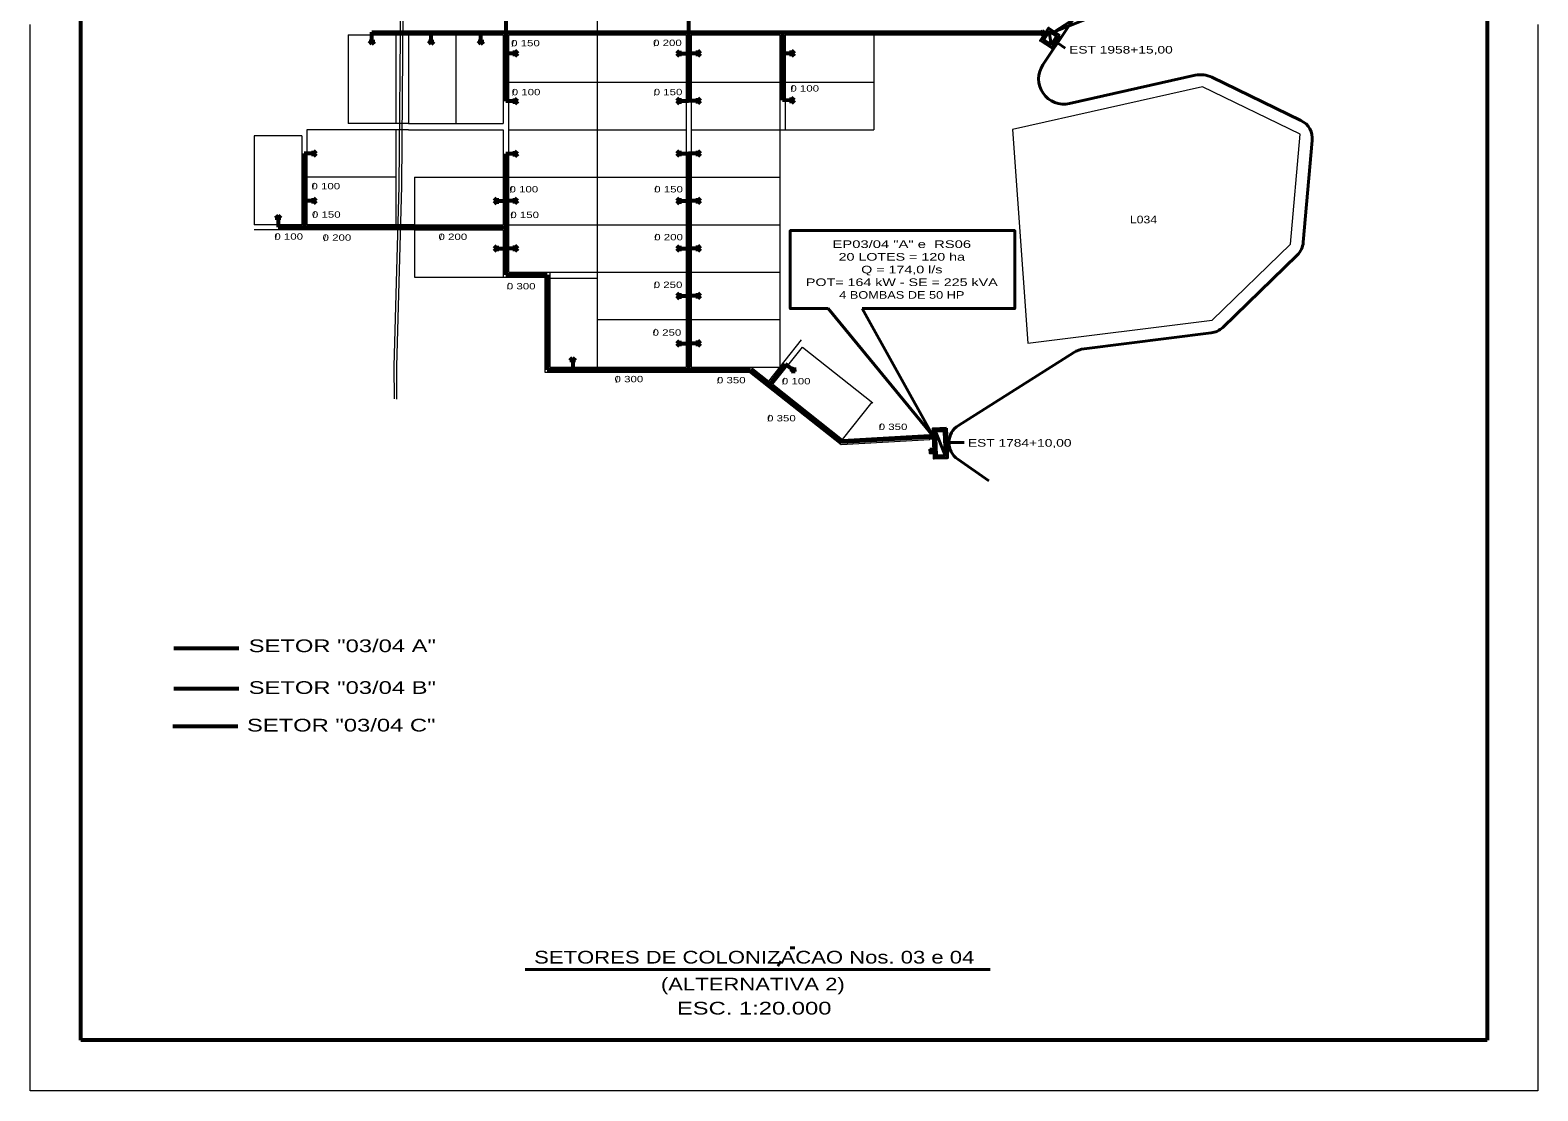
# Model space of a CAD drawing. Extents: x 312964 to 351929, y 9004151 to 9034973.
# Drawn here: x 326200 to 332140, y 9013358 to 9017535 of the extents above; entities that cross this region are included whole.
import ezdxf
from ezdxf.enums import TextEntityAlignment as Align

# ---------------------------------------------------------------- set-up
doc = ezdxf.new("R2010")
doc.units = 0
doc.header["$LTSCALE"] = 10
for name, color, linetype, lineweight in [('1', 7, 'Continuous', 13), ('2', 7, 'Continuous', 53), ('3', 7, 'Continuous', 13), ('6', 7, 'Continuous', 13)]:
    doc.layers.add(name, color=color, linetype=linetype, lineweight=lineweight)

msp = doc.modelspace()

# ---------------------------------------------------------------- linework, layer by layer
at = {"layer": '1', "lineweight": 53}
for p, q in [((326400.21, 9013557.86), (326400.21, 9021257.86)), ((331940.21, 9021257.86), (331940.21, 9013557.86)), ((326766.28, 9015101.17), (327022.23, 9015101.17)), ((326766.28, 9014942.16), (327022.23, 9014942.16)), ((331940.21, 9013557.86), (326400.21, 9013557.86))]:
    msp.add_line(p, q, dxfattribs=at)
at = {"layer": '1'}
for p, q in [((328434.4, 9018098.18), (328434.4, 9016208.18)), ((327453.4, 9017517.18), (328064.4, 9017517.18)), ((327453.4, 9017517.18), (327453.4, 9017167.18)), ((327640.4, 9017517.18), (327640.4, 9017167.18)), ((327690.4, 9017517.18), (327690.4, 9017167.18)), ((327877.4, 9017517.18), (327877.4, 9017167.18)), ((328064.4, 9017517.18), (328064.4, 9017167.18)), ((328084.4, 9017517.18), (328784.4, 9017517.18)), ((328084.4, 9017517.18), (328084.4, 9017143.18)), ((328784.4, 9017517.18), (328784.4, 9017143.18)), ((328804.4, 9017517.18), (329154.4, 9017517.18)), ((328804.4, 9017517.18), (328804.4, 9017143.18)), ((329154.4, 9017517.18), (329154.4, 9017143.18)), ((329174.4, 9017517.18), (330185.67, 9017517.18)), ((329174.4, 9017517.18), (329174.4, 9017143.18)), ((329524.4, 9017517.18), (329524.4, 9017143.18)), ((328084.4, 9017330.18), (328784.4, 9017330.18)), ((328804.4, 9017330.18), (329154.4, 9017330.18)), ((329174.4, 9017330.18), (329524.4, 9017330.18)), ((327690.4, 9017167.18), (327453.4, 9017167.18)), ((327690.4, 9017167.18), (328064.4, 9017167.18)), ((327083.4, 9017119.18), (327083.4, 9016769.18)), ((327270.4, 9017119.18), (327083.4, 9017119.18)), ((327270.4, 9017119.18), (327270.4, 9016769.18)), ((327690.4, 9017143.18), (327290.4, 9017143.18)), ((327290.4, 9017143.18), (327290.4, 9016769.18)), ((327640.4, 9017143.18), (327640.4, 9016769.18)), ((327690.4, 9017143.18), (328064.4, 9017143.18)), ((328064.4, 9017143.18), (328064.4, 9016769.18)), ((328084.4, 9017143.18), (328784.4, 9017143.18)), ((328084.4, 9017143.18), (328784.4, 9017143.18)), ((328084.4, 9017143.18), (328084.4, 9016582.18)), ((328784.4, 9017143.18), (328784.4, 9016208.18)), ((328804.4, 9017143.18), (329524.4, 9017143.18)), ((328804.4, 9017143.18), (328804.4, 9016208.18)), ((328804.4, 9017143.18), (329154.4, 9017143.18)), ((329154.4, 9017143.18), (329154.4, 9016208.18)), ((329174.4, 9017143.18), (329524.4, 9017143.18)), ((327640.4, 9016956.18), (327290.4, 9016956.18)), ((327714.4, 9016956.18), (328064.4, 9016956.18)), ((327714.4, 9016956.18), (327714.4, 9016769.18)), ((328084.4, 9016956.18), (328784.4, 9016956.18)), ((328804.4, 9016956.18), (329154.4, 9016956.18)), ((327270.4, 9016769.18), (327083.4, 9016769.18)), ((327236.67, 9016769.18), (327083.4, 9016769.18)), ((327714.4, 9016769.18), (327290.4, 9016769.18)), ((327714.4, 9016769.18), (328064.4, 9016769.18)), ((327714.4, 9016749.18), (328064.4, 9016749.18)), ((327714.4, 9016749.18), (327714.4, 9016562.18)), ((328064.4, 9016749.18), (328064.4, 9016562.18)), ((328084.4, 9016769.18), (328784.4, 9016769.18)), ((328804.4, 9016769.18), (329154.4, 9016769.18)), ((328084.4, 9016582.18), (328784.4, 9016582.18)), ((328247.4, 9016582.18), (328247.4, 9016208.18)), ((328804.4, 9016582.18), (329154.4, 9016582.18)), ((327714.4, 9016562.18), (328064.4, 9016562.18)), ((328064.4, 9016562.18), (328227.4, 9016562.18)), ((328227.4, 9016562.18), (328227.4, 9016188.18)), ((328247.4, 9016558.18), (328434.4, 9016558.18)), ((328434.4, 9016395.18), (328784.4, 9016395.18)), ((328804.4, 9016395.18), (329154.4, 9016395.18)), ((329110.89, 9016153.06), (329239.15, 9016315.53)), ((329126.58, 9016140.67), (329242.46, 9016287.44)), ((329242.46, 9016287.44), (329520.73, 9016067.75)), ((328247.4, 9016208.18), (328784.4, 9016208.18)), ((328804.4, 9016208.18), (329154.4, 9016208.18)), ((329041.07, 9016208.18), (329110.89, 9016153.06)), ((328227.4, 9016188.18), (329034.12, 9016188.18)), ((329034.12, 9016188.18), (329394.86, 9015903.39)), ((329126.58, 9016140.67), (329401.29, 9015923.79)), ((329401.29, 9015923.79), (329517.17, 9016070.57)), ((329394.86, 9015903.39), (329744.27, 9015923.47)), ((329401.29, 9015923.79), (329743.12, 9015943.43))]:
    msp.add_line(p, q, dxfattribs=at)
at = {"layer": '1', "lineweight": 40}
for p, q in [((330190.37, 9017399.2), (330425.64, 9017751.37)), ((330200.76, 9017525.23), (330179.99, 9017520.91)), ((330192.53, 9017512.68), (330188.21, 9017533.45)), ((330215.51, 9017529.5), (330222.42, 9017479.14)), ((330790.76, 9017357.5), (330295.47, 9017246.08)), ((331206.79, 9017179.77), (330856.38, 9017349.9)), ((331216.03, 9016699.82), (331251.54, 9017100.74)), ((330898.62, 9016364.83), (331192.04, 9016649.46)), ((330352.57, 9016280.45), (330852.83, 9016342.87)), ((329857.41, 9015978.67), (330311.52, 9016265.74)), ((329758.69, 9015929.02), (329743.12, 9015943.43)), ((329758.11, 9015944.01), (329743.7, 9015928.45)), ((329801.02, 9015957.32), (329802.49, 9015919.03)), ((329810.63, 9015967.7), (329812.87, 9015909.42)), ((329760.85, 9015870.74), (329745.31, 9015885.18)), ((329760.3, 9015885.73), (329745.85, 9015870.19)), ((329803.24, 9015898.95), (329804.63, 9015860.66)), ((329977.3, 9015760.07), (329854.53, 9015845.34)), ((329195.04, 9013921.59), (329213.33, 9013921.59)), ((328150.5, 9013836.35), (329981.83, 9013836.35)), ((329158.39, 9013869.07), (329145.73, 9013849.36))]:
    msp.add_line(p, q, dxfattribs=at)
at = {"layer": '1'}
for points in [[(332140.21, 9017557.86), (332140.21, 9013357.86), (326200.21, 9013357.86), (326200.21, 9017557.86)], [(330131.21, 9016303.21), (330856.6, 9016393.72), (331165.24, 9016693.12), (331203.56, 9017125.76), (330818.8, 9017312.56), (330070.41, 9017144.21)], [(327714.4, 9016749.18), (327290.4, 9016749.18), (327083.4, 9016749.18)]]:
    msp.add_lwpolyline(points, dxfattribs=at)
at = {"layer": '1', "lineweight": 40}
for points in [[(330188.21, 9017533.45), (330179.99, 9017520.91), (330192.53, 9017512.68), (330200.76, 9017525.23)], [(330257.28, 9017514.07), (330225.3, 9017465.29), (330180.65, 9017494.57), (330212.63, 9017543.34)], [(330243.44, 9017511.19), (330222.42, 9017479.14), (330194.5, 9017497.45), (330215.51, 9017529.5)], [(330215.51, 9017529.5), (330243.44, 9017511.19), (330222.42, 9017479.14)], [(329743.12, 9015943.43), (329743.7, 9015928.45), (329758.69, 9015929.02), (329758.11, 9015944.01)], [(329767.66, 9015956.05), (329801.02, 9015957.32), (329804.63, 9015860.66)], [(329745.31, 9015885.18), (329745.85, 9015870.19), (329760.85, 9015870.74), (329760.3, 9015885.73)]]:
    msp.add_lwpolyline(points, close=True, dxfattribs=at)
for points in [[(329759.52, 9015907.37), (329757.28, 9015965.65), (329810.63, 9015967.7)], [(329769.87, 9015897.74), (329767.66, 9015956.05), (329801.02, 9015957.32)], [(329812.87, 9015909.31), (329814.98, 9015851.02), (329761.63, 9015849.09), (329759.52, 9015907.37)], [(329803.24, 9015898.95), (329804.63, 9015860.66), (329771.26, 9015859.45), (329769.87, 9015897.74)]]:
    msp.add_lwpolyline(points, dxfattribs=at)
for centre, radius, start, end in [((330273.52, 9017343.65), 100, 146.25469, 282.67773), ((330812.71, 9017259.94), 100, 64.10269, 102.67774), ((331171.85, 9017107.8), 80, 354.93858, 64.10274), ((331136.34, 9016706.88), 80, 314.12934, 354.9386), ((330842.92, 9016422.25), 80, 277.11219, 314.12931), ((330364.95, 9016181.22), 100, 97.11218, 122.3), ((329900.16, 9015911.05), 80, 122.29999, 235.22056)]:
    msp.add_arc(centre, radius, start, end, dxfattribs=at)
at = {"layer": '2', "lineweight": 40}
for p, q in [((330545.86, 9017730.28), (330234.96, 9017528.71)), ((330550.35, 9017653.91), (330234.96, 9017528.71)), ((330247.91, 9017485.33), (330278.33, 9017465.01)), ((329820.17, 9015911.97), (329879.5, 9015911.29))]:
    msp.add_line(p, q, dxfattribs=at)
at = {"layer": '2'}
for p, q in [((327546.78, 9017491.33), (327546.9, 9017527.18)), ((327779.73, 9017491.33), (327779.85, 9017527.18)), ((327976.1, 9017491.33), (327976.22, 9017527.18)), ((329164.4, 9017527.18), (329164.4, 9017259.07)), ((327536.26, 9017491.37), (327557.82, 9017491.3)), ((327547, 9017480.55), (327536.26, 9017491.37)), ((327547, 9017480.55), (327557.82, 9017491.3)), ((327769.21, 9017491.37), (327790.76, 9017491.3)), ((327779.95, 9017480.55), (327769.21, 9017491.37)), ((327779.95, 9017480.55), (327790.76, 9017491.3)), ((327965.58, 9017491.37), (327987.14, 9017491.3)), ((327976.32, 9017480.55), (327965.58, 9017491.37)), ((327976.32, 9017480.55), (327987.14, 9017491.3)), ((328110.21, 9017433.04), (328110.29, 9017454.6)), ((328121.03, 9017443.78), (328110.29, 9017454.6)), ((328830.21, 9017433.04), (328830.29, 9017454.6)), ((328841.03, 9017443.78), (328830.29, 9017454.6)), ((329200.21, 9017433.04), (329200.29, 9017454.6)), ((329211.03, 9017443.78), (329200.29, 9017454.6)), ((330241.29, 9017489.68), (330247.88, 9017485.28)), ((328110.25, 9017443.56), (328074.4, 9017443.68)), ((328121.03, 9017443.78), (328110.21, 9017433.04)), ((328747.77, 9017443.58), (328758.59, 9017454.32)), ((328747.77, 9017443.58), (328758.52, 9017432.76)), ((328758.59, 9017454.32), (328758.52, 9017432.76)), ((328758.55, 9017443.8), (328794.4, 9017443.68)), ((328830.25, 9017443.56), (328794.4, 9017443.68)), ((328841.03, 9017443.78), (328830.21, 9017433.04)), ((329200.25, 9017443.56), (329164.4, 9017443.68)), ((329211.03, 9017443.78), (329200.21, 9017433.04)), ((328110.25, 9017255.3), (328074.4, 9017255.42)), ((328110.21, 9017244.78), (328110.29, 9017266.34)), ((328121.03, 9017255.52), (328110.21, 9017244.78)), ((328121.03, 9017255.52), (328110.29, 9017266.34)), ((328747.77, 9017256.58), (328758.59, 9017267.32)), ((328747.77, 9017256.58), (328758.52, 9017245.76)), ((328758.59, 9017267.32), (328758.52, 9017245.76)), ((328758.55, 9017256.8), (328794.4, 9017256.68)), ((328830.25, 9017256.56), (328794.4, 9017256.68)), ((328830.21, 9017246.04), (328830.29, 9017267.6)), ((328841.03, 9017256.78), (328830.21, 9017246.04)), ((328841.03, 9017256.78), (328830.29, 9017267.6)), ((329200.25, 9017258.95), (329164.4, 9017259.07)), ((329200.21, 9017248.43), (329200.29, 9017269.99)), ((329211.03, 9017259.17), (329200.21, 9017248.43)), ((329211.03, 9017259.17), (329200.29, 9017269.99)), ((327280.4, 9017049.62), (327280.4, 9016759.18)), ((327316.25, 9017049.5), (327280.4, 9017049.62)), ((327316.21, 9017038.97), (327316.29, 9017060.53)), ((327327.03, 9017049.72), (327316.21, 9017038.97)), ((327327.03, 9017049.72), (327316.29, 9017060.53)), ((328074.4, 9017048.41), (328074.4, 9016572.18)), ((328110.25, 9017048.29), (328074.4, 9017048.41)), ((328110.21, 9017037.77), (328110.29, 9017059.33)), ((328121.03, 9017048.51), (328110.21, 9017037.77)), ((328121.03, 9017048.51), (328110.29, 9017059.33)), ((328747.77, 9017049.58), (328758.59, 9017060.32)), ((328747.77, 9017049.58), (328758.52, 9017038.76)), ((328758.59, 9017060.32), (328758.52, 9017038.76)), ((328758.55, 9017049.8), (328794.4, 9017049.68)), ((328794.4, 9017049.68), (328794.4, 9016198.18)), ((328830.25, 9017049.56), (328794.4, 9017049.68)), ((328830.21, 9017039.04), (328830.29, 9017060.6)), ((328841.03, 9017049.78), (328830.21, 9017039.04)), ((328841.03, 9017049.78), (328830.29, 9017060.6)), ((327316.25, 9016862.56), (327280.4, 9016862.68)), ((327316.21, 9016852.04), (327316.29, 9016873.6)), ((327327.03, 9016862.78), (327316.21, 9016852.04)), ((327327.03, 9016862.78), (327316.29, 9016873.6)), ((328027.77, 9016862.58), (328038.59, 9016873.32)), ((328027.77, 9016862.58), (328038.52, 9016851.76)), ((328038.59, 9016873.32), (328038.52, 9016851.76)), ((328038.55, 9016862.8), (328074.4, 9016862.68)), ((328110.25, 9016862.56), (328074.4, 9016862.68)), ((328110.21, 9016852.04), (328110.29, 9016873.6)), ((328121.03, 9016862.78), (328110.21, 9016852.04)), ((328121.03, 9016862.78), (328110.29, 9016873.6)), ((328747.77, 9016862.58), (328758.59, 9016873.32)), ((328747.77, 9016862.58), (328758.52, 9016851.76)), ((328758.59, 9016873.32), (328758.52, 9016851.76)), ((328758.55, 9016862.8), (328794.4, 9016862.68)), ((328830.25, 9016862.56), (328794.4, 9016862.68)), ((328830.21, 9016852.04), (328830.29, 9016873.6)), ((328841.03, 9016862.78), (328830.21, 9016852.04)), ((328841.03, 9016862.78), (328830.29, 9016873.6)), ((327176.8, 9016805.81), (327165.98, 9016795.07)), ((327176.8, 9016805.81), (327187.54, 9016794.99)), ((327187.54, 9016794.99), (327165.98, 9016795.07)), ((327177.02, 9016795.03), (327176.9, 9016759.18)), ((327176.9, 9016759.18), (328074.4, 9016759.18)), ((328027.77, 9016675.58), (328038.59, 9016686.32)), ((328038.59, 9016686.32), (328038.52, 9016664.76)), ((328110.21, 9016665.04), (328110.29, 9016686.6)), ((328121.03, 9016675.78), (328110.29, 9016686.6)), ((328747.77, 9016675.58), (328758.59, 9016686.32)), ((328758.59, 9016686.32), (328758.52, 9016664.76)), ((328830.21, 9016665.04), (328830.29, 9016686.6)), ((328841.03, 9016675.78), (328830.29, 9016686.6)), ((328027.77, 9016675.58), (328038.52, 9016664.76)), ((328038.55, 9016675.8), (328074.4, 9016675.68)), ((328110.25, 9016675.56), (328074.4, 9016675.68)), ((328121.03, 9016675.78), (328110.21, 9016665.04)), ((328747.77, 9016675.58), (328758.52, 9016664.76)), ((328758.55, 9016675.8), (328794.4, 9016675.68)), ((328830.25, 9016675.56), (328794.4, 9016675.68)), ((328841.03, 9016675.78), (328830.21, 9016665.04)), ((328074.4, 9016572.18), (328237.4, 9016572.18)), ((328237.4, 9016572.18), (328237.4, 9016198.18)), ((328747.77, 9016488.58), (328758.59, 9016499.32)), ((328747.77, 9016488.58), (328758.52, 9016477.76)), ((328758.59, 9016499.32), (328758.52, 9016477.76)), ((328758.55, 9016488.8), (328794.4, 9016488.68)), ((328830.25, 9016488.56), (328794.4, 9016488.68)), ((328830.21, 9016478.04), (328830.29, 9016499.6)), ((328841.03, 9016488.78), (328830.21, 9016478.04)), ((328841.03, 9016488.78), (328830.29, 9016499.6)), ((328747.77, 9016301.58), (328758.59, 9016312.32)), ((328747.77, 9016301.58), (328758.52, 9016290.76)), ((328758.59, 9016312.32), (328758.52, 9016290.76)), ((328758.55, 9016301.8), (328794.4, 9016301.68)), ((328830.25, 9016301.56), (328794.4, 9016301.68)), ((328830.21, 9016291.04), (328830.29, 9016312.6)), ((328841.03, 9016301.78), (328830.21, 9016291.04)), ((328841.03, 9016301.78), (328830.29, 9016312.6)), ((328337.51, 9016244.81), (328326.69, 9016234.07)), ((328348.25, 9016233.99), (328326.69, 9016234.07)), ((328337.51, 9016244.81), (328348.25, 9016233.99)), ((328337.73, 9016234.03), (328337.61, 9016198.18)), ((329204.73, 9016197.94), (329176.67, 9016220.25)), ((328237.4, 9016198.18), (329037.6, 9016198.18)), ((329198.19, 9016189.71), (329211.6, 9016206.58)), ((329213.33, 9016191.44), (329198.19, 9016189.71)), ((329213.33, 9016191.44), (329211.6, 9016206.58)), ((329112.54, 9016139.02), (329398.08, 9015913.59)), ((329398.08, 9015913.59), (329743.7, 9015933.45)), ((329812.87, 9015909.42), (329820.17, 9015909.56)), ((326762.05, 9014794.08), (327018, 9014794.08))]:
    msp.add_line(p, q, dxfattribs=at)
for points in [[(328074.4, 9018003.02), (328074.4, 9017527.18), (328074.4, 9017255.42)], [(328794.4, 9018002.65), (328794.4, 9017527.18), (328794.4, 9017256.68)], [(327546.9, 9017527.18), (328064.4, 9017527.18), (328784.4, 9017527.18), (329154.4, 9017527.18), (330184.1, 9017527.18)], [(329037.6, 9016198.18), (329112.54, 9016139.02), (329176.67, 9016220.25)]]:
    msp.add_lwpolyline(points, dxfattribs=at)
at = {"layer": '2', "lineweight": 40}
for points in [[(329195.16, 9016655.42), (329195.16, 9016745.85), (329372.65, 9016745.85)], [(329372.65, 9016745.85), (330079.39, 9016745.85), (330079.39, 9016439.03), (329478.8, 9016439.03)], [(329344.14, 9016439.03), (329195.16, 9016439.03), (329195.16, 9016655.42)], [(329344.14, 9016439.03), (329758.4, 9015936.51), (329478.8, 9016439.03)]]:
    msp.add_lwpolyline(points, dxfattribs=at)
at = {"layer": '3'}
msp.add_line((330070.41, 9017144.21), (330131.21, 9016303.21), dxfattribs=at)
at = {"layer": '6'}
for p, q in [((327654.4, 9016921.26), (327664.4, 9018138.26)), ((327634.41, 9016210.46), (327654.41, 9016921.46)), ((327635.24, 9016082.67), (327634.4, 9016210.12))]:
    msp.add_line(p, q, dxfattribs=at)
msp.add_lwpolyline([(327645.24, 9016081.85), (327644.4, 9016210.18), (327664.4, 9016921.18), (327674.4, 9018138.18)], dxfattribs=at)

# ---------------------------------------------------------------- texts
at = {"layer": '1'}
for s, width, p in [('SETOR "03/04 A"', 1.4, (327430.05, 9015085.66)), ('SETOR "03/04 B"', 1.4, (327430.05, 9014921.17)), ('SETOR "03/04 C"', 1.4, (327425.82, 9014773.08)), ('SETORES DE COLONIZACAO Nos. 03 e 04', 1.3, (329052.89, 9013859.22)), ('(ALTERNATIVA 2)', 1.3, (329047.45, 9013753.1)), ('ESC. 1:20.000', 1.4, (329052.71, 9013658.46))]:
    msp.add_text(s, height=50, dxfattribs=dict(at, width=width)).set_placement(p, align=Align.CENTER)
at = {"layer": '2'}
for s, height, width, p in [('0 150', 25, 1.35, (328151.63, 9017471.88)), ('0 200', 25, 1.35, (328710.87, 9017472.94)), ('EST 1958+15,00', 30, 1.35, (330497.73, 9017443.15)), ('0 100', 25, 1.35, (328154.01, 9017278.99)), ('0 150', 25, 1.35, (328713.38, 9017279.19)), ('0 100', 25, 1.35, (329251.83, 9017293.49)), ('0 100', 25, 1.35, (327364.96, 9016908.5)), ('0 100', 25, 1.35, (328145.37, 9016896.19)), ('0 150', 25, 1.35, (328715.49, 9016896.19)), ('0 150', 25, 1.35, (327366.94, 9016796.67)), ('0 150', 25, 1.35, (328148.48, 9016795.19)), ('0 100', 25, 1.35, (327218.85, 9016710.06)), ('0 200', 25, 1.35, (327408.89, 9016705.83)), ('0 200', 25, 1.35, (327865.6, 9016709.2)), ('0 200', 25, 1.35, (328715.55, 9016707.77)), ('EP03/04 "A" e  RS06', 30, 1.45, (329634.34, 9016677.51)), ('20 LOTES = 120 ha', 30, 1.4, (329634.34, 9016627.51)), ('Q = 174,0 l/s', 30, 1.4, (329634.34, 9016577.51)), ('0 300', 25, 1.35, (328134.82, 9016514.3)), ('0 250', 25, 1.35, (328713.38, 9016520.11)), ('POT= 164 kW - SE = 225 kVA', 30, 1.4, (329634.34, 9016527.51)), ('4 BOMBAS DE 50 HP', 30, 1.25, (329634.34, 9016477.51)), ('0 250', 25, 1.35, (328709.16, 9016332.03)), ('0 300', 25, 1.35, (328559.24, 9016148.7)), ('0 350', 25, 1.35, (328962.55, 9016144.47)), ('0 100', 25, 1.35, (329218.34, 9016140.38)), ('0 350', 25, 1.35, (329159.99, 9015994.38)), ('0 350', 25, 1.35, (329599.87, 9015960.69)), ('EST 1784+10,00', 30, 1.35, (330098.91, 9015894.84))]:
    msp.add_text(s, height=height, dxfattribs=dict(at, width=width)).set_placement(p, align=Align.CENTER)
for p in [(328102.05, 9017469.37), (328661.9, 9017472.2), (328104.43, 9017277.53), (328662.1, 9017276.2), (329202.79, 9017292.74), (327316.62, 9016908.4), (328096.03, 9016894.85), (328664.85, 9016896.79), (327318.59, 9016796.57), (328098.36, 9016794.12), (327169.48, 9016709.4), (327361.63, 9016704.12), (327818.34, 9016707.49), (328664.85, 9016707.65), (328083.21, 9016514.95), (328662.74, 9016518.51), (328659.66, 9016333.2), (328511.85, 9016146.18), (328911.64, 9016143.05), (329168.82, 9016140.11), (329110.47, 9015994.12), (329550.34, 9015960.43)]:
    msp.add_text('/', height=25, dxfattribs=at).set_placement(p, align=Align.CENTER)
at = {"layer": '3', "width": 1.2}
msp.add_text('L034', height=30, dxfattribs=at).set_placement((330586.47, 9016774.52), align=Align.CENTER)

doc.saveas('drawing.dxf')
